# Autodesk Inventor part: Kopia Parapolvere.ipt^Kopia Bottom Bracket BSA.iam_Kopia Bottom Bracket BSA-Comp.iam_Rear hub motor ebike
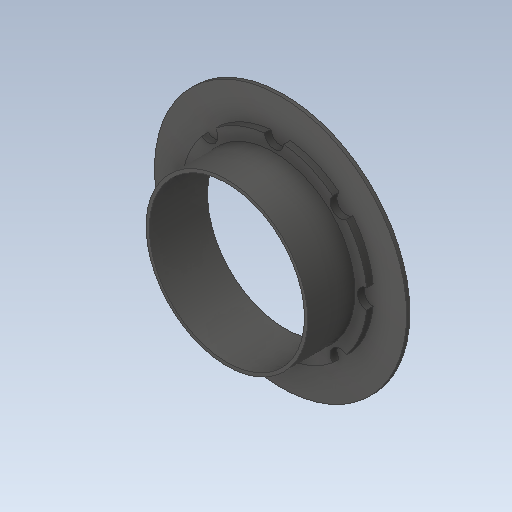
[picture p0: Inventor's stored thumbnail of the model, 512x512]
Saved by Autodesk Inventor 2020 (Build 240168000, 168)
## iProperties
Created: 2017-11
Part Number: Kopia Parapolvere.ipt^Kopia Bottom Bracket BSA.iam_Kopia Bottom Bracket BSA-Comp.iam_Rear hub motor ebike
Material: Ogólny
Document SubType Name: Modeling
Designer: Tomasz
Density: 1 g/cm^3
Appearance: Domyślna
Sending System: SolidWorks 2017
Last Author: Tomasz
Last Saved: 2017-11-19
Author: Tomasz
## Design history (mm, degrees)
feature "Parapolvere.ipt"
node "Bryła1"
